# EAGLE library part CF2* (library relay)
NEW DUAL POWER AUTOMOTIVE RELAY NAiS Source: http://www.mew-europe.com/.. en_ds_61203_0000.pdf
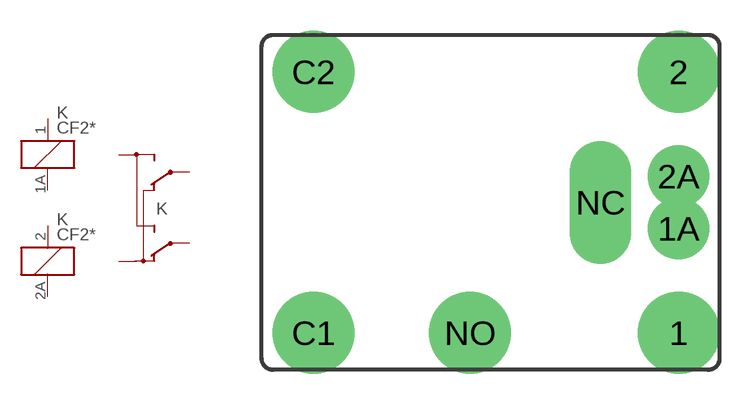
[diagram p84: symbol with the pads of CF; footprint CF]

Designator prefix K; gates 1-1=K 1-2=K 2=CF

## CF2-12V (OC_FARNELL: unknown; OC_NEWARK: unknown)  [CF]
1  1-1:1  pas
1A  1-1:2  pas
2  1-2:1  pas
2A  1-2:2  pas
C1  2:COM1  pas
C2  2:COM2  pas
NC  2:NC  pas
NO  2:NO  pas

## Footprint CF (pad centres in mm)
NEW DUAL POWER AUTOMOTIVE RELAY NAiS Source: http://www.mew-europe.com/.. en_ds_61203_0000.pdf
drill 1.5 pad 4 round: 1 9.16,-6.35; 2 9.16,6.35; C1 -8.62,-6.35; C2 -8.62,6.35; NO -1,-6.35
drill 1.5 pad 3 round: 1A 9.16,-1.27; 2A 9.16,1.27
drill 1.5 pad 3 long: NC 5.35,0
